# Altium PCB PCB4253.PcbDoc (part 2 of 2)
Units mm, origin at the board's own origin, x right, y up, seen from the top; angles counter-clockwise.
Board outline 30 x 51 mm, 6 copper layers (Top Layer, Signal Layer 2, GND Layer 3, PWR Layer 4, Signal Layer 5, Bottom Layer), stack 1.656 mm thick; 84 components, 108 nets, 396 pads, 436 vias.
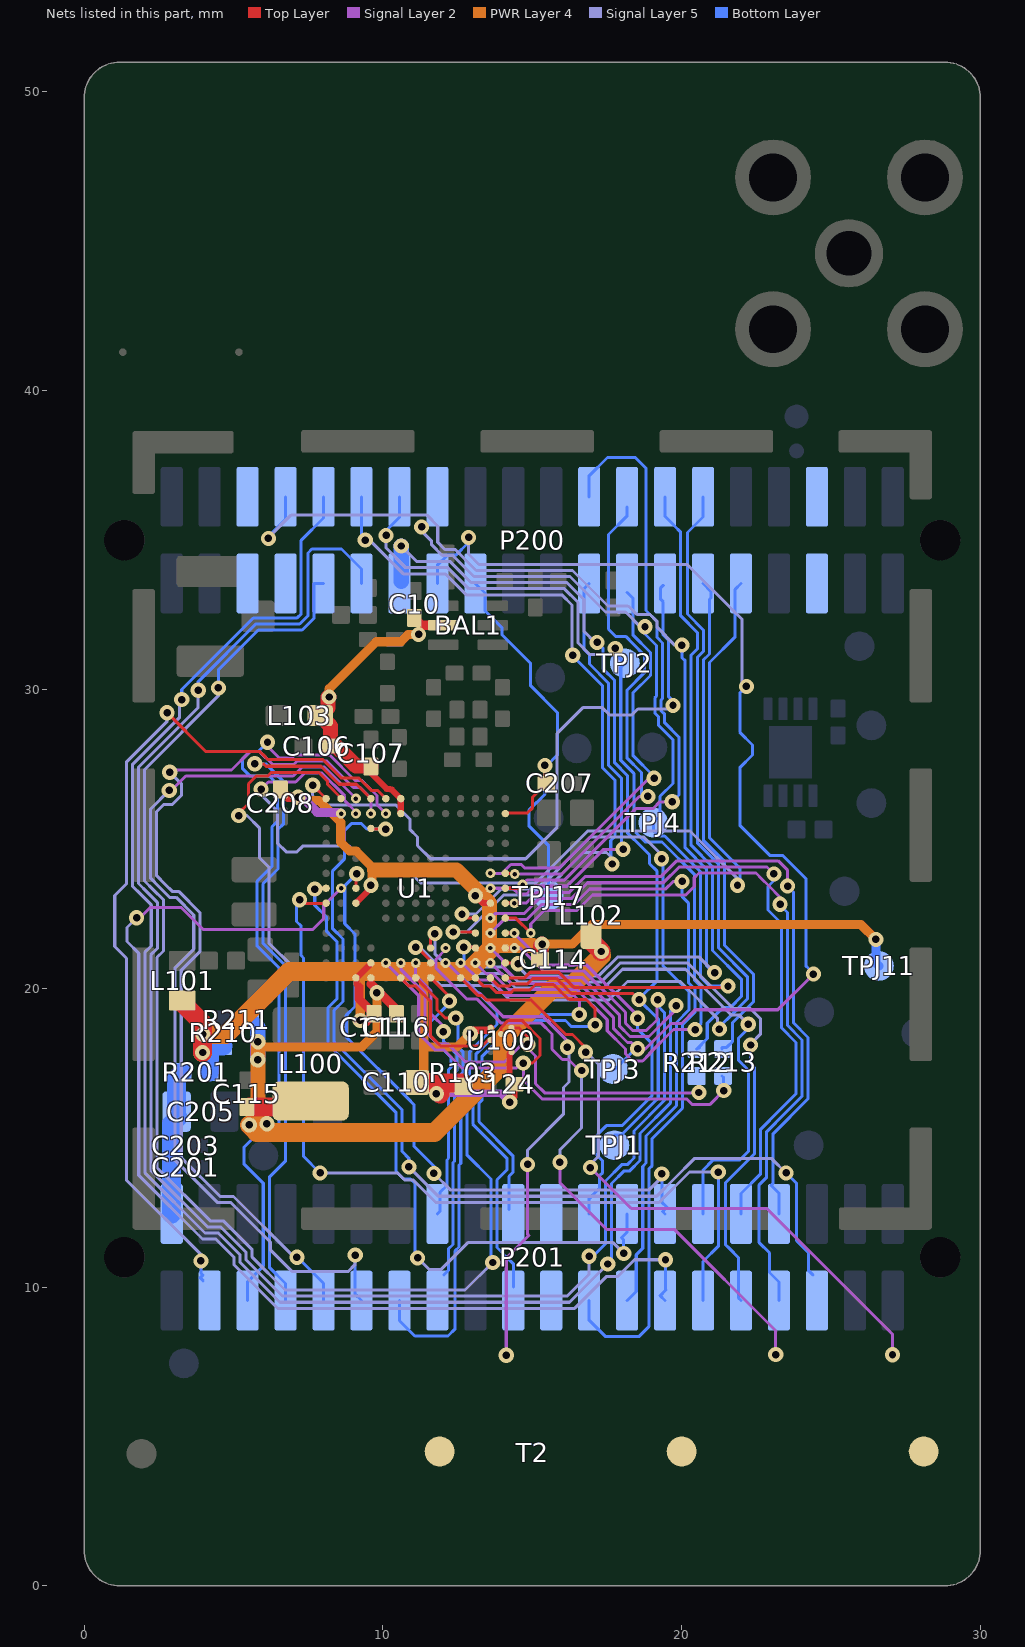
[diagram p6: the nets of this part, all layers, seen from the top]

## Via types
v1: diameter 0.508, hole 0.25, Top Layer to Bottom Layer, tented both sides, 404 vias
v2: diameter 0.33/0.33 (per signal layer), hole 0.15, Top Layer to Signal Layer 2, tented both sides, 31 vias
v3: diameter 0.33/0.33 (per signal layer), hole 0.15, Top Layer to Signal Layer 2, tented top, 1 vias

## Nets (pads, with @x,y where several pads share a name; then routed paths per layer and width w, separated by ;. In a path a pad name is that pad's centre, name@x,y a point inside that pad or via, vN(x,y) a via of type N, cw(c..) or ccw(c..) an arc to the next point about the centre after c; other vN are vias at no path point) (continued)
RADIO_PC1: T2.2 U1.B5 | length 16.6
  Signal Layer 2 w0.102: v2(12.1,20.85) 12.154,20.85 12.283,20.722 12.283,20.718 13.162,19.839 13.24,19.839 14.03,19.049 15.373,19.049 16.176,18.246 v1(16.176,18.026) ; v1(14.13,7.721) 14.13,10.974 14.884,11.728 14.845,11.767 v1(14.845,14.109)
  Signal Layer 5 w0.102: v1(14.845,14.109) 14.845,14.59 16.041,15.786 16.047,15.786 16.047,16.681 16.232,16.866 16.232,17.369 16.233,17.37 16.233,17.968 v1(16.176,18.026)
RADIO_PC2: T2.3 U1.C5 | length 21.5
  Signal Layer 2 w0.102: v3(12.1,21.35) 12.1,21.299 11.783,20.982 11.783,20.666 12.813,19.636 13.155,19.636 13.946,18.846 15.271,18.846 15.288,18.846 15.664,18.471 15.664,17.963 16.007,17.619 16.212,17.619 16.581,17.251 v1(16.651,17.251) ; v1(15.926,14.183) 15.926,13.494 16.239,13.181 17.484,11.936 19.753,11.936 23.159,8.531 23.148,8.519 v1(23.148,7.743)
  Signal Layer 5 w0.102: v1(15.926,14.183) 15.926,14.603 16.651,15.328 v1(16.651,17.251)
RADIO_PC3: T2.4 U1.A4 | length 22.7
  Top Layer w0.102: U1.A4@12.6,20.35 13.196,19.754 13.321,19.754 13.471,19.604 14.967,19.604 16.118,18.453 16.344,18.453 16.801,17.997 16.786,17.982 v1(16.786,17.861) ; v1@27.125,7.773 v1@27.166,7.732
  Signal Layer 2 w0.102: v1(16.949,14.001) 18.316,12.634 22.851,12.634 27.056,8.428 v1(27.056,7.736)
  Signal Layer 5 w0.102: v1(16.786,17.861) 16.816,17.861 17.218,17.459 17.218,14.379 16.949,14.11 v1(16.949,14.001)
RADIO_PC4: P201.19 U1.B4 | length 17.6
  Signal Layer 2 w0.102: v2(12.6,20.85) 12.651,20.85 13.225,20.276 13.614,20.276 14.13,19.76 16.394,19.76 16.576,19.578 v1(16.576,19.126)
  Bottom Layer w0.102: P201.19@14.365,10.004 14.365,10.785 13.821,11.329 13.821,13.591 14.149,13.92 14.149,14.317 13.013,15.453 13.013,15.621 13.015,15.622 13.015,16.235 13.11,16.331 13.11,17.796 14.44,19.126 v1(16.576,19.126)
RADIO_PC5: P201.20 U1.A3 | length 15.3
  Top Layer w0.102: U1.A3@13.1,20.35 13.377,20.073 13.59,20.073 13.794,19.868 14.298,19.868 14.373,19.944 14.918,19.944 15.106,20.132 15.717,20.132 16.223,19.626 16.797,19.626 17.101,19.322 v1(17.101,18.776)
  Bottom Layer w0.102: P201.20@14.224,12.591 14.224,13.707 14.352,13.835 14.352,14.401 13.217,15.537 13.218,15.538 13.218,16.151 13.313,16.246 13.313,17.712 14.524,18.923 16.111,18.923 16.315,18.72 17.044,18.72 v1(17.101,18.776)
RADIO_PC6: R213.1 U1.B9 U100.D2 | length 18.3
  Top Layer w0.102: U100.D2@13.958,18.471 13.958,18.685 14.201,18.928 14.648,18.928 15.257,18.319 15.257,17.749 15.009,17.501 v1(14.701,17.501)
  Signal Layer 2 w0.102: v2(10.1,20.85) 11.201,19.749 11.201,18.487 11.754,17.935 12.05,17.935 12.649,17.335 14.466,17.335 v1@14.683,17.551 ; v1(14.701,17.501) 14.701,16.93 15.331,16.3 20.172,16.3 20.364,16.108 20.936,16.108 v1(21.406,16.578)
  Bottom Layer w0.102: R213.1@21.351,17.065 21.406,17.01 v1(21.406,16.578)
RADIO_PC7: U1.A8 U100.C3 | length 4.7
  Top Layer w0.102: U1.A8@10.6,20.35 10.877,20.073 11.09,20.073 11.602,19.56 11.602,18.399 11.927,18.075 13.023,18.075 13.024,18.074 13.329,18.074 13.525,18.271 U100.C3@13.608,18.271
RADIO_PC8: R212.1 U1.B8 U100.E1 | length 14.7
  Top Layer w0.102: U100.E1@14.308,18.671 14.549,18.671 14.851,18.369 14.849,18.367 14.851,18.365 v1(14.851,18.126)
  Signal Layer 2 w0.102: v2(10.6,20.85) 10.6,20.637 11.405,19.833 11.405,18.571 11.838,18.138 12.175,18.138 12.775,17.538 14.07,17.538 14.682,18.151 14.826,18.151 v1(14.851,18.126) ; v1@14.771,18.071 15.107,17.735 15.107,16.811 15.415,16.503 20.566,16.503 v1(20.578,16.514)
RADIO_PC9: P201.13 U1.A7 | length 15.6
  Top Layer w0.102: U1.A7@11.1,20.35 11.806,19.644 11.806,19.293 12.096,19.003 v1(12.438,19.003)
  Bottom Layer w0.102: P201.13@10.555,9.55 10.555,8.879 11.071,8.363 12.18,8.363 12.421,8.603 12.421,11.216 12.551,11.346 12.551,14.09 12.607,14.146 12.607,17.108 12.688,17.189 12.688,17.863 12.519,18.032 12.519,18.922 v1(12.438,19.003)
RADIO_PC10: P201.15 U1.B7 | length 11.1
  Signal Layer 2 w0.102: v2(11.1,20.85) 11.1,20.425 11.608,19.917 11.608,19.149 v1@12.111,18.646
  Bottom Layer w0.102: v1(12.026,18.551) 12.026,18.238 12.485,17.778 12.485,17.273 12.404,17.192 12.404,14.23 12.347,14.174 12.347,11.43 12.192,11.275 12.192,10.557 P201.15@12.04,10.404
RADIO_PC11: P201.16 U1.A6 | length 9.3
  Top Layer w0.102: U1.A6@11.6,20.35 12.371,19.579 12.42,19.628 12.357,19.691 12.242,19.576 v1(12.226,19.576)
  Bottom Layer w0.102: P201.16@11.825,12.45 11.913,12.538 11.913,13.171 12.144,13.403 12.144,14.258 12.201,14.315 12.201,17.276 12.282,17.358 12.282,17.694 11.594,18.382 11.594,18.874 12.226,19.505 v1(12.226,19.576)
RADIO_PD8: P201.3 U1.N9 | length 29.7
  Top Layer w0.102: v1(2.781,29.223) 4.085,27.92 5.883,27.92 5.971,27.832 5.978,27.832 6.158,27.652 7.999,27.652 8.616,27.034 9.204,27.034 9.61,26.627 9.823,26.627 U1.N9@10.1,26.35
  Signal Layer 5 w0.102: v1(2.781,29.223) 2.781,28.936 1.415,27.569 1.415,23.493 1.028,23.106 1.028,21.401 1.424,21.005 1.424,13.577 3.988,11.013 3.933,10.959 3.977,10.916 3.938,10.877 v1(3.912,10.877)
  Bottom Layer w0.102: v1(3.912,10.877) 3.912,10.468 3.977,10.403 3.886,10.312 P201.3@3.988,10.21
RADIO_PD9: P201.5 U1.M9 | length 27.2
  Signal Layer 2 w0.102: v1(6.14,28.239) 6.14,28.105 6.544,27.701 6.941,27.701 7.054,27.813 8.211,27.813 9.068,26.956 9.299,26.956 9.803,26.452 9.803,26.147 v2(10.1,25.85)
  Bottom Layer w0.102: P201.5@5.475,9.55 5.475,10.182 5.997,10.704 5.997,13.48 5.348,14.13 5.348,14.67 5.7,15.023 ; 5.738,15.061 6.289,15.061 6.532,15.304 6.532,20.68 5.788,21.424 5.788,23.58 6.289,24.081 6.289,25.405 6.477,25.593 6.477,26.831 6.201,27.107 5.543,27.107 5.543,27.111 5.309,27.345 5.309,27.682 5.547,27.92 5.821,27.92 v1(6.14,28.239)
RADIO_PD10: P201.7 U1.N10 | length 24
  Top Layer w0.102: v1(5.715,27.514) 6.009,27.514 6.091,27.432 7.931,27.432 8.532,26.831 9.119,26.831 U1.N10@9.6,26.35
  Bottom Layer w0.102: v1(5.715,27.514) 6.082,27.514 6.68,26.915 6.68,25.509 6.492,25.321 6.492,23.997 5.992,23.496 5.992,21.508 6.735,20.764 6.735,14.213 6.201,13.678 6.201,10.664 6.745,10.12 P201.7@6.745,9.55
RADIO_PD11: P201.9 U1.M10 | length 30.4
  Signal Layer 2 w0.102: v1(2.87,27.234) 2.945,27.309 4.936,27.309 5.547,27.92 5.883,27.92 6.306,27.497 7.025,27.497 7.138,27.61 8.127,27.61 9.014,26.724 9.244,26.724 9.6,26.367 v2(9.6,25.85)
  Signal Layer 5 w0.102: v1(2.87,27.234) 3.257,26.848 3.257,26.456 2.953,26.153 2.666,26.153 2.431,25.918 2.431,23.764 2.723,23.472 2.947,23.248 3.168,23.248 3.875,22.541 3.875,21.229 3.253,20.607 3.253,14.335 4.556,13.031 5,13.031 7.031,11.001 v1(7.125,11.001)
  Bottom Layer w0.102: v1(7.125,11.001) 6.981,11.001 6.938,11.044 7.019,11.125 7.442,10.702 7.821,10.323 8.015,10.129 P201.9@8.015,9.55
RADIO_PD12: P201.11 U1.N11 | length 30.4
  Signal Layer 2 w0.102: v1(2.851,26.625) 2.925,26.625 3.406,27.106 6.031,27.106 ; 6.031,27.106 6.998,27.106 7.299,27.407 8.043,27.407 v2(9.1,26.35)
  Signal Layer 5 w0.102: v1(2.851,26.625) 2.228,26.002 2.228,23.68 2.519,23.388 2.863,23.045 3.084,23.045 3.672,22.456 3.672,21.313 3.05,20.691 3.05,14.25 4.472,12.828 4.916,12.828 6.235,11.508 6.235,11.254 6.97,10.52 8.832,10.52 9.075,10.763 v1(9.075,11.076)
  Bottom Layer w0.102: v1(9.075,11.076) 9.075,9.76 P201.11@9.285,9.55
RADIO_PD13: P200.31 U1.M11 | length 35
  Signal Layer 2 w0.102: v1(5.926,26.662) 6.166,26.903 7.082,26.903 7.384,27.204 7.959,27.204 8.721,26.441 8.721,26.28 9.1,25.901 v2(9.1,25.85)
  Signal Layer 5 w0.102: v1(5.926,26.662) 5.926,26.481 6.477,25.93 6.477,24.856 6.766,24.567 7.128,24.567 7.317,24.756 8.881,24.756 9.522,24.115 10.674,24.115 11.265,23.524 15.115,23.524 16.858,25.267 20.277,25.267 21.996,23.548 21.898,23.45 v1(21.869,23.45)
  Bottom Layer w0.102: v1(21.869,23.45) 21.951,23.45 21.951,24.016 20.93,25.038 20.93,30.903 21.79,31.763 21.79,33.355 P200.31@21.985,33.55
RADIO_PD14: P200.30 U1.N12 | length 46.3
  Top Layer w0.102: v1(5.179,25.782) 5.179,25.86 5.502,26.183 5.502,26.846 5.764,27.107 6.149,27.107 6.265,27.223 7.852,27.223 8.153,26.922 8.153,26.819 8.6,26.372 U1.N12@8.6,26.35
  Signal Layer 5 w0.102: v1(5.179,25.782) 5.456,25.782 5.867,25.371 5.867,24.378 6.198,24.048 6.198,21.502 6.965,20.735 11.298,20.735 11.936,20.097 13.76,20.097 14.25,19.607 17.564,19.607 18.189,20.232 19.958,20.232 21.206,18.984 21.206,18.821 21.342,18.685 v1@21.307,18.649 ; v1(21.263,18.634) 21.291,18.634 v1@21.307,18.649 ; v1@21.31,18.646 v1@21.307,18.649
  Bottom Layer w0.102: P200.30@20.715,36.45 20.715,35.776 20.193,35.254 20.193,32.53 20.727,31.996 20.727,31.276 20.523,31.072 20.523,24.869 21.238,24.155 21.238,21.35 22.2,20.388 22.2,19.641 21.708,19.15 21.706,19.15 21.285,18.729 21.34,18.674 21.31,18.644 21.305,18.649 21.29,18.634 v1(21.263,18.634)
RADIO_PD15: P200.27 U1.N13 | length 22.6
  Top Layer w0.102: v1(7.653,26.797) U1.N13@8.1,26.35
  Signal Layer 5 w0.102: v1(7.653,26.797) 7.653,26.438 7.948,26.142 10.429,26.142 10.905,25.666 10.905,25.319 11.163,25.062 11.163,24.776 11.602,24.337 14.778,24.337 15.834,25.393 15.834,28.535 16.693,29.394 17.345,29.394 17.595,29.145 18.33,29.145 18.533,29.348 19.589,29.348 v1(19.71,29.47)
  Bottom Layer w0.102: P200.27@19.384,33.489 19.298,33.403 19.298,33.022 19.383,32.937 19.383,31.826 19.565,31.643 19.565,29.755 v1@19.742,29.578
RADIO_PF0: P200.14 TPJ2.1 U1.B3 | length 36.2
  Signal Layer 2 w0.102: v2(13.1,20.85) 13.471,20.479 13.698,20.479 14.214,19.963 16.491,19.963 17.51,18.945 17.51,18.58 18.12,17.97 18.12,17.808 18.358,17.569 18.694,17.569 18.932,17.808 18.932,17.83 19.725,18.622 19.726,18.621 v1(20.45,18.621)
  Signal Layer 5 w0.102: v1(10.109,35.159) 10.109,34.737 10.77,34.076 12.175,34.076 12.877,33.374 16.076,33.374 16.535,32.915 16.535,31.558 16.922,31.171 17.577,31.171 v1(17.78,31.375)
  Bottom Layer w0.102: v1(10.109,35.159) 10.273,35.159 10.293,35.18 10.269,35.18 10.119,35.329 10.555,35.765 P200.14@10.555,36.45 ; v1(17.78,31.375) 17.751,31.375 17.678,31.302 TPJ2.1@18.1,30.88 17.961,30.741 17.961,29.353 17.961,28.509 17.961,27.631 18.398,27.195 18.398,25.28 18.78,24.898 19.345,24.898 20.425,23.818 20.425,20.281 20.653,20.053 20.653,18.835 20.45,18.632 v1(20.45,18.621)
RADIO_PF1: P200.13 TPJ1.1 U1.A2 | length 34
  Top Layer w0.102: U1.A2@13.6,20.35 13.878,20.072 14.214,20.072 14.289,20.147 14.834,20.147 15.022,20.335 15.802,20.335 16.307,19.829 18.373,19.829 v1(18.576,19.626)
  Signal Layer 5 w0.102: v1(10.617,34.804) 11.141,34.28 12.259,34.28 12.961,33.578 16.16,33.578 16.739,32.999 16.739,31.94 v1@17.093,31.585
  Bottom Layer w0.102: v1(17.17,31.578) 17.374,31.375 17.374,30.684 17.758,30.299 17.758,29.268 17.758,28.593 17.758,27.547 18.183,27.122 18.183,25.207 18.696,24.694 18.923,24.467 18.923,24.17 19.179,23.914 19.179,20.252 18.576,19.648 v1(18.576,19.626) ; TPJ1.1@17.75,14.75 17.75,15.093 17.982,15.093 19.217,16.328 19.217,18.971 18.566,19.621 v1@18.551,19.621
  Bottom Layer w0.508: P200.13@10.617,33.612 v1(10.617,34.804)
RADIO_PF2: P200.15 TPJ3.1 U1.B2 | length 40.6
  Signal Layer 2 w0.102: v2(13.6,20.851) 13.614,20.851 14.298,20.166 16.576,20.166 17.713,19.029 17.713,18.664 18.189,18.188 18.314,18.188 v1(18.526,17.976) 18.791,17.976 19.642,18.827 19.993,18.827 20.451,19.284 23.219,19.284 v1(24.411,20.476)
  Signal Layer 5 w0.102: v1(12.867,35.093) 12.867,34.534 13.213,34.187 20.183,34.187 22.017,32.352 22.017,30.252 v1(22.167,30.103)
  Bottom Layer w0.102: P200.15@11.825,33.55 11.825,34.16 12.162,34.497 12.444,34.497 12.867,34.92 v1(12.867,35.093) ; TPJ3.1@17.7,17.3 17.777,17.3 18.466,17.989 18.491,17.963 18.504,17.976 v1(18.526,17.976) 18.554,17.976 v1@18.593,18.014 ; v1(22.167,30.103) 21.946,29.881 21.946,28.574 22.372,28.147 22.372,27.812 21.946,27.385 21.946,25.458 22.963,24.441 23.391,24.441 24.155,23.677 24.155,20.754 v1@24.264,20.645
RADIO_PF3: P200.16 TPJ4.1 U1.A1 | length 31.1
  Top Layer w0.102: U1.A1@14.1,20.35 14.749,20.35 14.938,20.538 15.886,20.538 16.392,20.032 21.507,20.032 v1(21.551,20.076)
  Signal Layer 5 w0.102: v1(11.297,35.441) 11.384,35.441 11.384,35.217 11.634,34.967 11.634,34.841 11.992,34.483 12.343,34.483 13.045,33.781 16.263,33.781 17.45,32.594 18.126,32.594 18.617,32.103 v1(18.773,32.103)
  Bottom Layer w0.102: v1(18.773,32.103) 18.773,31.861 19.159,31.475 19.159,29.78 19.101,29.722 19.101,29.217 19.228,29.09 19.228,28.804 19.71,28.321 19.71,26.856 19.279,26.424 19.279,26.075 19.28,26.074 19.28,25.78 TPJ4.1@19.05,25.55 19.05,25.285 19.234,25.101 19.43,25.101 20.628,23.902 20.628,20.366 20.918,20.076 v1(21.551,20.076)
RADIO_PF4: P200.23 U1.G2 | length 14.7
  Signal Layer 2 w0.102: v2(13.6,23.35) 14.351,23.35 14.544,23.157 14.808,23.157 15.068,23.417 16.155,23.417 17.391,24.653 v1(18.042,24.653)
  Bottom Layer w0.102: P200.23@16.905,33.55 16.739,33.384 16.739,31.34 16.916,31.162 16.916,30.854 17.555,30.215 17.555,29.184 17.555,28.677 17.555,27.463 17.98,27.038 17.98,24.697 18.024,24.653 v1(18.042,24.653)
RADIO_PF5: P200.24 U1.G1 | length 21.7
  Top Layer w0.102: U1.G1@14.1,23.35 14.55,23.35 v2(14.675,23.475) ; v2@14.667,23.5 v2@14.675,23.492 ; v2(14.675,23.475) v2@14.675,23.492 ; v2(14.675,23.475) 14.683,23.483 v2@14.675,23.492
  Signal Layer 2 w0.102: v2@14.71,23.44 v2(14.675,23.475) 14.821,23.621 16.071,23.621 18.466,26.015 19.041,26.015 19.269,26.244 v1(19.685,26.244)
  Bottom Layer w0.102: P200.24@16.905,36.45 16.905,37.155 17.519,37.769 18.449,37.769 18.808,37.409 18.808,32.645 19.179,32.274 19.179,31.742 19.362,31.559 19.362,29.696 19.304,29.638 19.304,29.301 19.431,29.174 19.431,28.888 19.914,28.405 19.914,26.472 v1(19.685,26.244)
RADIO_PF6: P200.25 U1.H2 | length 14
  Signal Layer 2 w0.102: v2(13.6,23.85) 13.99,23.85 14.282,24.141 14.635,24.141 14.749,24.027 15.903,24.027 18.907,27.031 v1(19.075,27.031)
  Bottom Layer w0.102: P200.25@18.175,33.25 18.364,33.061 18.364,31.83 18.956,31.239 18.956,30.473 18.368,29.885 18.368,28.34 18.368,27.8 19.075,27.092 v1(19.075,27.031)
RADIO_PF7: P200.26 U1.H1 | length 17.1
  Top Layer w0.102: U1.H1@14.1,23.85 14.387,23.85 v2(14.413,23.824)
  Signal Layer 2 w0.102: v2(14.413,23.824) 15.987,23.824 18.585,26.422 v1(18.872,26.422)
  Bottom Layer w0.102: P200.26@18.175,36.114 18.175,35.812 17.551,35.188 17.551,32.019 17.789,31.781 18.126,31.781 18.364,31.543 18.364,31.538 18.752,31.15 18.752,30.557 18.164,29.969 18.164,29.437 18.164,28.424 18.164,27.716 18.659,27.221 18.659,26.422 v1@18.791,26.422
RADIO_PF8: P200.8 U1.B1 | length 38
  Top Layer w0.102: U1.B1@14.1,20.85 14.563,20.85 14.601,20.812 14.661,20.872 14.614,20.826 v1(14.526,20.826)
  Signal Layer 5 w0.102: v1(6.172,35.058) 6.172,35.082 6.938,35.848 11.465,35.848 11.837,35.475 11.837,34.925 12.076,34.686 12.427,34.686 13.129,33.984 16.347,33.984 17.534,32.797 18.21,32.797 18.498,32.509 18.941,32.509 19.179,32.271 19.179,32.08 19.773,31.486 v1(20.007,31.486) ; v1(14.526,20.826) 14.651,20.826 14.661,20.836 14.602,20.778 14.605,20.778 14.539,20.712 14.48,20.772 14.478,20.77 14.828,20.42 17.228,20.42 17.852,21.045 20.586,21.045 v1(21.104,20.526)
  Bottom Layer w0.102: v1@6.125,35.075 6.745,35.695 P200.8@6.745,36.45 ; v1(20.007,31.486) 20.007,31.074 20.117,30.965 20.117,24.701 20.831,23.986 20.831,20.754 21.104,20.481 v1(21.104,20.526)
RADIO_PF9: P200.9 U1.C3 | length 49.1
  Top Layer w0.102: v1(12.708,21.381) 13.069,21.381 U1.C3@13.1,21.35
  Signal Layer 5 w0.102: v1(4.496,30.054) 4.496,29.788 2.024,27.317 2.024,23.596 2.316,23.304 2.656,22.965 2.656,21.252 2.44,21.036 2.44,13.998 4.22,12.218 4.663,12.218 5.626,11.256 5.626,11.002 6.726,9.902 12.752,9.902 v1(13.676,10.826)
  Bottom Layer w0.102: v1(4.496,30.054) 4.496,30.65 5.835,31.99 7.302,31.99 7.696,32.384 7.696,33.55 P200.9@8.015,33.55 ; v1(12.708,21.381) 12.708,20.324 13.818,19.215 13.818,18.792 12.907,17.881 12.907,16.415 12.811,16.319 12.811,15.706 12.81,15.705 12.81,15.368 12.81,14.427 13.617,13.62 13.617,10.884 v1(13.676,10.826)
RADIO_PF10: P200.10 U1.C2 | length 62.4
  Signal Layer 2 w0.102: v2(13.6,21.35) 13.998,20.952 13.998,20.754 14.382,20.37 16.66,20.37 17.916,19.113 17.916,18.748 18.273,18.391 18.909,18.391 19.815,19.298 v1(19.815,19.423)
  Signal Layer 5 w0.102: v1(3.27,29.664) 3.188,29.582 3.188,29.055 1.618,27.485 1.618,23.428 1.91,23.136 2.249,22.796 2.249,21.42 2.034,21.205 2.034,13.83 4.051,11.812 4.495,11.812 5.219,11.087 5.219,10.833 6.558,9.495 16.246,9.495 v1(17.526,10.775)
  Bottom Layer w0.102: v1(3.27,29.664) 3.27,29.999 5.667,32.396 6.521,32.396 6.523,32.398 7.135,32.398 7.267,32.53 7.267,34.992 8.015,35.74 P200.10@8.015,36.45 ; v1(17.526,10.775) 17.653,10.902 17.653,13.47 18.077,13.894 18.264,13.894 18.606,14.236 18.606,15.142 19.623,16.159 19.623,19.231 v1(19.815,19.423)
RADIO_PF11: P200.11 U1.C1 | length 61.4
  Top Layer w0.102: U1.C1@14.1,21.35 v2(14.4,21.35)
  Signal Layer 2 w0.102: v2(14.4,21.35) 14.599,21.35 15.376,20.573 16.744,20.573 18.12,19.197 18.12,18.833 18.358,18.595 18.824,18.595 19.174,18.944 19.174,19.585 v1(19.205,19.617)
  Signal Layer 5 w0.102: v1(3.821,29.975) 3.821,29.401 1.821,27.401 1.821,23.512 2.113,23.22 2.453,22.88 2.453,21.336 2.237,21.12 2.237,13.914 4.135,12.015 4.579,12.015 5.423,11.172 5.423,10.918 6.642,9.699 16.162,9.699 16.903,10.44 v1(16.903,11.033)
  Bottom Layer w0.102: v1(3.821,29.975) 3.821,30.263 5.751,32.193 7.217,32.193 7.493,32.468 7.493,34.57 7.625,34.702 8.618,34.702 9.285,34.036 P200.11@9.285,33.55 ; v1(16.903,11.033) 17.03,11.033 17.449,11.452 17.449,13.554 17.993,14.098 18.18,14.098 18.402,14.32 18.402,15.226 19.42,16.244 19.42,19.192 19.205,19.406 v1(19.205,19.617)
RADIO_PF12: P200.12 U1.D3 | length 26.1
  Top Layer w0.102: v1(12.351,21.885) 13.065,21.885 U1.D3@13.1,21.85
  Signal Layer 5 w0.102: v1(9.414,35) 9.559,35 10.686,33.873 12.091,33.873 12.793,33.171 15.992,33.171 16.332,32.831 16.332,31.171 v1(16.358,31.146) ; v1(12.351,21.885) 12.807,21.885 14.039,23.118 15.283,23.118 16.714,24.548 17.484,24.548 17.671,24.361 v1(17.671,24.162)
  Bottom Layer w0.102: P200.12@9.285,36.45 9.285,35.129 v1(9.414,35) ; v1(16.358,31.146) 16.358,31.125 17.352,30.131 17.352,29.1 17.352,28.761 17.352,27.379 17.777,26.954 17.777,25.097 17.627,24.946 17.627,24.207 v1(17.671,24.162)
RADIO_PF13: P201.23 U1.D2 | length 25.9
  Signal Layer 2 w0.102: v2(13.6,21.85) 14.047,22.297 14.809,22.297 15.32,22.808 16.408,22.808 16.93,23.33 19.47,23.33 19.717,23.577 v1(20.015,23.577)
  Bottom Layer w0.102: P201.23@16.905,9.55 16.905,8.892 17.455,8.342 18.564,8.342 18.901,8.678 18.901,13.956 19.012,14.068 19.012,14.974 20.029,15.991 20.029,18.775 20.45,19.196 20.45,19.969 20.222,20.197 20.222,22.861 20.015,23.067 v1(20.015,23.577)
RADIO_PF14: P201.24 U1.D1 | length 13.8
  Top Layer w0.102: U1.D1@14.1,21.85 v2(14.4,21.85)
  Signal Layer 2 w0.102: v2(14.4,21.85) 14.4,21.837 15.461,20.776 16.828,20.776 18.526,19.078 v1(18.526,19.001) v1@18.538,19.001
  Bottom Layer w0.102: P201.24@16.905,12.45 16.905,12.961 17.246,13.302 17.246,13.724 17.355,13.832 17.355,14.222 17.098,14.48 17.098,15.02 17.48,15.402 18.004,15.402 19.013,16.412 19.013,18.146 18.526,18.633 v1(18.526,19.001)
RADIO_PF15: P201.25 U1.E3 | length 24.7
  Top Layer w0.102: v1(12.649,22.485) 12.715,22.485 12.85,22.35 U1.E3@13.1,22.35
  Signal Layer 5 w0.102: v1(12.649,22.485) 13.118,22.485 13.955,23.321 15.199,23.321 16.942,25.064 18.731,25.064 19.329,24.466 v1(19.329,24.339)
  Bottom Layer w0.102: P201.25@18.175,9.55 18.481,9.856 18.481,11.081 18.697,11.298 18.697,14.04 18.809,14.152 18.809,15.058 19.826,16.075 19.826,18.86 20.247,19.28 20.247,19.885 19.382,20.749 19.382,24.286 v1(19.329,24.339)
RADIO_PI0: P201.26 U1.G13 | length 23.6
  Top Layer w0.102: v1(7.722,23.323) 7.749,23.35 U1.G13@8.1,23.35
  Signal Layer 5 w0.102: v1@11.187,10.98 v1(11.161,10.98) 11.544,10.597 11.959,10.597 12.862,11.501 17.689,11.501 v1(18.059,11.131)
  Bottom Layer w0.102: v1(7.722,23.323) 7.722,22.78 8.115,22.386 8.115,21.911 8.46,21.566 8.46,19.643 8.165,19.348 8.165,18.125 8.186,18.104 10.435,15.856 10.435,13.888 10.703,13.62 10.927,13.62 11.077,13.47 11.077,11.064 v1(11.161,10.98) ; v1(18.059,11.131) 18.059,11.581 17.985,11.655 18.175,11.845 P201.26@18.175,12.45
RADIO_PI1: P201.27 U1.G12 | length 38.8
  Signal Layer 2 w0.102: v1(1.758,22.36) 1.876,22.36 2.226,22.709 3.246,22.709 3.98,21.975 7.659,21.975 8.022,22.337 8.022,22.772 v2(8.6,23.35)
  Signal Layer 5 w0.102: v1(1.758,22.36) 1.437,22.039 1.437,21.568 1.83,21.174 1.83,13.745 3.967,11.609 4.411,11.609 5.016,11.003 5.016,10.749 6.474,9.292 16.418,9.292 17.49,10.364 17.867,10.364 18.42,10.917 v1(19.459,10.917)
  Bottom Layer w0.102: P201.27@19.445,9.55 19.28,9.715 19.475,9.911 19.459,9.927 v1(19.459,10.917)
RADIO_PI2: P201.28 U1.G11 | length 21.9
  Top Layer w0.102: U1.G11@9.1,23.35 9.1,23.85 9.119,23.831 v1(9.125,23.837)
  Signal Layer 5 w0.102: v1(11.709,13.806) 12.27,13.245 18.903,13.245 19.335,13.677 v1(19.335,13.788)
  Bottom Layer w0.102: v1(9.125,23.837) 8.725,23.437 8.725,22.163 9.07,21.818 9.07,19.391 8.775,19.096 8.775,18.378 8.796,18.357 10.83,16.323 11.044,16.108 11.044,14.716 11.709,14.051 v1(11.709,13.806) ; v1(19.335,13.788) 19.335,12.845 19.507,12.674 19.364,12.531 P201.28@19.445,12.45
RADIO_PI3: P201.29 U1.F13 | length 29.4
  Top Layer w0.102: v1(7.214,22.967) 7.217,22.967 7.237,22.947 7.134,22.844 7.176,22.844 7.274,22.942 7.372,22.844 8.094,22.844 U1.F13@8.1,22.85
  Signal Layer 5 w0.102: v1(7.899,13.823) 10.5,13.823 10.744,13.579 11.024,13.579 11.765,12.838 19.248,12.838 20.26,13.851 v1(21.226,13.851)
  Bottom Layer w0.102: v1(7.214,22.967) 7.112,22.866 7.112,22.24 7.265,22.087 7.265,21.435 ; 7.264,21.434 7.264,21.097 7.345,21.017 7.345,14.378 v1(7.899,13.823) ; P201.29@20.715,9.55 20.715,10.862 21.237,11.384 21.237,13.839 v1(21.226,13.851)
RADIO_PJ14: P201.30 U1.B6 | length 21.3
  Top Layer w0.102: v1(11.094,21.371) 11.148,21.371 11.6,20.919 U1.B6@11.6,20.85
  Signal Layer 5 w0.102: v1(11.094,21.371) 11.237,21.371 12.104,20.503 13.947,20.503 14.437,20.014 17.396,20.014 18.021,20.638 20.126,20.638 21.652,19.113 21.914,19.113 v1(22.226,18.801)
  Bottom Layer w0.102: P201.30@20.715,12.45 20.715,13.914 21.062,14.262 21.951,14.262 22.235,14.546 22.235,17.261 21.895,17.601 21.895,18.119 21.902,18.127 21.902,18.335 22.226,18.659 v1(22.226,18.801)
RADIO_PJ15: P201.31 U1.C6 | length 24.2
  Top Layer w0.102: U1.C6@11.585,21.365 U1.C6@11.6,21.35 11.6,21.689 v1(11.741,21.831)
  Signal Layer 5 w0.102: v1(11.741,21.831) 11.741,21.154 12.188,20.707 14.031,20.707 14.521,20.217 17.312,20.217 17.937,20.842 20.211,20.842 21.736,19.317 22.305,19.317 22.632,18.989 22.632,18.461 22.338,18.166 22.429,18.075 22.305,17.951 22.284,17.972 22.309,17.996 v1(22.309,18.104)
  Bottom Layer w0.102: P201.31@21.985,9.55 21.905,9.63 21.905,10.987 21.595,11.297 21.463,11.43 21.463,13.486 22.438,14.462 22.438,17.345 22.301,17.482 22.301,17.951 22.284,17.968 22.309,17.992 v1(22.309,18.104)
RADIO_PK0: P201.32 U1.E2 | length 22.9
  Signal Layer 2 w0.102: v2(13.6,22.35) 13.75,22.5 14.725,22.5 15.236,23.011 16.324,23.011 16.846,23.534 19.386,23.534 19.916,24.063 22.856,24.063 v1(23.089,23.831)
  Bottom Layer w0.102: P201.32@21.985,12.45 21.985,13.137 22.643,13.795 22.643,15.289 23.25,15.895 23.41,16.056 23.825,16.471 23.825,18.19 23.338,18.677 23.338,22.17 22.886,22.621 22.886,23.409 23.089,23.611 v1(23.089,23.831)
RADIO_PK1: P201.33 U1.E1 | length 25.6
  Top Layer w0.102: U1.E1@14.1,22.35 14.45,22.35 v2(14.95,21.85)
  Signal Layer 2 w0.102: v2(14.95,21.85) 14.95,22.15 15.404,22.605 16.492,22.605 17.015,23.127 20.14,23.127 20.422,23.408 20.422,23.703 20.578,23.86 22.485,23.86 22.682,23.663 22.92,23.424 23.293,23.052 v1(23.293,22.815)
  Bottom Layer w0.102: P201.33@23.255,9.55 23.255,10.172 22.937,10.49 22.937,11.148 22.595,11.491 22.595,13.425 22.846,13.676 22.846,15.205 23.453,15.811 23.495,15.853 24.028,16.387 24.028,18.274 23.541,18.761 23.541,22.54 23.293,22.789 v1(23.293,22.815)
RADIO_PK2: P201.34 U1.F1 | length 22.3
  Top Layer w0.102: U1.F1@14.1,22.85 v2(14.4,22.85)
  Signal Layer 2 w0.102: v2(14.4,22.85) 14.788,22.85 15.152,23.214 16.239,23.214 16.762,23.737 19.302,23.737 19.831,24.266 23.228,24.266 23.546,23.948 v1(23.546,23.424)
  Bottom Layer w0.102: P201.34@23.255,12.45 23.255,13.145 22.993,13.407 23.049,13.463 23.049,15.12 24.232,16.303 24.232,18.358 23.744,18.846 23.744,23.231
USB_VBUS: P200.35
USB_VREG: P200.36
VBIAS: BAL1.2 C10.1 C106.1 C107.1 L103.2 U1.M8 U1.N8 | length 10.8
  Top Layer w0.203: C107.1@9.6,27.425 9.6,27.209 10.131,26.678 10.236,26.678 10.264,26.65 10.3,26.65 U1.N8@10.6,26.35 U1.M8@10.6,25.85 ; C10.1@11.05,32.4 C10.1@11.125,32.325
  Top Layer w0.305: C10.1@11.125,32.325 11.3,32.15 BAL1.2@12.024,32.15
  Top Layer w0.508: v1(8.2,29.75) 8.166,29.75 8.166,29.391 L103.2@7.9,29.125 8.243,28.782 C106.1@8.243,28.107 8.438,28.107 9.105,27.44 9.6,27.44 C107.1@9.6,27.425
  PWR Layer 4 w0.305: v1(8.2,29.75) 8.2,30.025 9.775,31.6 10.6,31.6 10.845,31.845 v1(11.195,31.845)
VDCDC: C115.1 C116.1 L100.2 L102.1 R211.2 U1.A10 | length 28
  Top Layer w0.203: U1.A10@9.6,20.35 9.6,20.15 9.606,20.144
  Top Layer w0.305: 9.606,20.15 9.606,20.144 v1@9.8,19.95 ; v1(9.8,19.85) v1@9.8,19.95 ; C116.1@10.45,19.15 10.45,19.3 v1@9.8,19.95
  Top Layer w0.635: C115.1@5.532,16.025 L100.2@6.949,16.025 ; L102.1@16.972,21.746 16.972,21.573 17.304,21.241 v1@17.304,21.233
  PWR Layer 4 w0.305: 6.083,18.036 9.298,18.036 9.8,18.538 v1(9.8,19.85)
  PWR Layer 4 w0.508: 5.819,15.467 v1(5.819,18.212)
  PWR Layer 4 w0.635: v1(5.532,15.429) 5.778,15.183 11.73,15.183 14.009,17.462 14.009,18.327 15.666,19.984 16.206,19.984 v1@17.313,21.091
  Bottom Layer w0.508: R211.2@5.558,18.955 5.813,18.701 v1(5.813,17.611)
  other v1: 6.121,15.467 17.313,21.233
VMCU: C110.1 C111.1 C114.1 C124.1 C208.1 L101.1 R103.1 R201.2 R210.2 TPJ11.1 U1.A11 U1.B10 U1.F2 U1.F11 U1.M12 U100.A1 U100.E3 | length 61.6
  Top Layer w0.203: U1.F11@9.1,22.85 9.6,23.35 v1(9.6,23.45) ; 9.2,20.05 9.121,20.129 9.121,20.329 U1.A11@9.1,20.35 9.121,20.35 9.6,20.829 U1.B10@9.6,20.85 ; v1(13.1,23.1) 13.35,22.85 U1.F2@13.6,22.85 ; C124.1@14.289,16.673 C124.1@14.289,16.791 ; U100.A1@14.308,17.871 14.244,17.807 14.244,16.959 C124.1@14.411,16.791 14.411,16.359 v1@14.272,16.219 ; v1@14.272,16.219 14.298,16.193 v1(14.245,16.193) v1@14.272,16.219
  Top Layer w0.254: v1(12.926,18.481) 13.049,18.604 13.541,18.604 U100.E3@13.608,18.671
  Top Layer w0.305: C208.1@6.569,26.651 6.824,26.396 v1(7.163,26.396) ; 9.2,20.05 9.2,19.65 C111.1@9.7,19.15 v1@9.429,18.879
  Top Layer w0.508: C114.1@15.284,20.972 15.284,21.434 v1(15.33,21.481)
  Top Layer w0.635: L101.1@3.285,19.511 3.97,18.826 ; v1(3.97,17.853) 3.97,18.815 ; C110.1@11.15,16.85 11.921,16.85 ; v1@11.921,16.471 11.921,16.85 ; R103.1@12.679,16.837 11.933,16.837 11.921,16.85
  Signal Layer 2 w0.254: v1@11.81,16.489 13.949,16.489 v1(14.245,16.193) ; v1@11.877,16.428 v1@11.915,16.465
  Signal Layer 2 w0.305: v1(7.163,26.396) 7.297,26.396 7.805,25.888 8.562,25.888 v2(8.6,25.85)
  PWR Layer 4 w0.305: 7.409,26.289 7.858,26.289 8.592,25.555 8.592,24.89 8.89,24.592 9.111,24.592 9.633,24.069 v1@9.633,23.483 ; 9.209,20.563 9.246,20.527 v1(9.246,18.929) ; 11.367,20.563 11.367,16.937 v1@11.877,16.428 ; 11.389,18.043 12.487,18.043 v1(12.926,18.481) ; v1(15.33,21.481) 16.337,21.481 16.907,22.051 16.911,22.051 16.994,22.134 26.002,22.134 v1(26.499,21.637)
  PWR Layer 4 w0.508: 9.723,23.96 12.468,23.96 13.57,22.857 13.57,21.373 13.617,21.326 ; 13.693,21.402 13.727,21.436 15.028,21.436 15.062,21.402 v1@15.33,21.402
  PWR Layer 4 w0.635: v1(3.97,17.853) v1@3.97,18.457 ; v1(3.977,18.457) 4.753,18.457 6.864,20.569 8.129,20.569 8.135,20.563 9.209,20.563 12.855,20.563 13.617,21.326 13.693,21.402
  Bottom Layer w0.305: v1(26.499,21.637) 26.499,20.85 TPJ11.1@26.6,20.75
  Bottom Layer w0.635: v1(3.977,18.457) 3.977,17.861 4.182,18.066 R210.2@4.658,18.066 ; R201.2@4.2,17.2 v1@4.2,17.853
  other v1: 11.794,16.474
VMCU_IN: C201.1 C203.1 C205.1 P201.2 R201.1 | length 4.7
  Bottom Layer w0.635: P201.2@2.935,12.45 2.933,12.452 2.933,15.469 C205.1@3.139,15.674 ; C205.1@3.1,15.875 3.1,17 R201.1@3.3,17.2
WSTK_F4: C207.1 P200.17 TPJ17.1 U1.M1 | length 15.2
  Top Layer w0.102: U1.M1@14.1,25.85 14.119,25.869 14.837,25.869 15.015,26.047 15.015,26.404 C207.1@15.309,26.698 ; v1(15.423,27.461) 15.423,27.077 C207.1@15.556,26.945 ; C207.1@15.468,26.857 C207.1@15.309,26.698 ; C207.1@15.5,27 15.309,26.809 C207.1@15.309,26.698
  Bottom Layer w0.102: P200.17@13.095,33.55 13.418,33.227 13.418,32.636 13.992,32.063 13.992,31.825 14.948,30.869 14.948,30.124 15.838,29.234 15.838,27.807 15.492,27.461 v1(15.423,27.461) 15.423,26.499 14.898,25.973 14.898,25.423 15.55,24.771 TPJ17.1@15.55,23.1
WSTK_F15: P200.28 R212.2 | length 20.6
  Bottom Layer w0.102: P200.28@19.445,36.45 19.445,35.794 19.744,35.496 19.744,35.491 19.967,35.267 19.967,32.468 20.524,31.911 20.524,31.36 20.32,31.156 20.32,24.785 21.035,24.07 21.035,21.266 21.996,20.304 21.996,19.725 21.624,19.353 21.373,19.353 20.856,18.836 20.856,18.751 20.856,18.363 20.858,18.361 20.858,18.32 R212.2@20.504,17.966 20.59,18.051 R212.2@20.59,18.009
WSTK_F16: P200.29 R213.2 | length 17
  Bottom Layer w0.102: P200.29@20.715,33.55 20.975,33.29 20.975,33.064 20.93,33.02 20.93,31.191 20.726,30.987 20.726,24.953 21.441,24.239 21.441,21.434 22.403,20.473 22.403,19.551 22.059,19.207 ; R213.2@21.351,17.965 21.351,18.027 21.508,18.027 21.699,18.218 21.699,18.849 22.058,19.207
WSTK_P18: P201.21
WSTK_P19: P201.22
WSTK_P32: P201.35 U1.L10 | length 32.3
  Top Layer w0.102: U1.L10@9.6,25.35 9.648,25.302 9.676,25.329 v1(10.092,25.329)
  Signal Layer 5 w0.102: v1(10.871,14.026) 11.856,13.042 19.164,13.042 19.742,13.62 20.421,14.299 23.019,14.299 v1(23.495,13.823)
  Bottom Layer w0.102: v1(10.092,25.329) 9.465,25.329 9.284,25.511 8.947,25.511 8.709,25.273 8.709,24.321 8.319,23.931 8.319,21.995 8.663,21.65 8.663,19.559 8.368,19.264 8.368,18.209 8.389,18.188 10.638,15.94 10.638,14.547 10.871,14.314 v1(10.871,14.026) ; v1(23.495,13.823) 23.849,13.47 23.849,11.557 24.238,11.168 24.238,10.563 P201.35@24.388,10.413
WSTK_P38: P200.5
WSTK_P39: P200.6
WSTK_P40: P200.7
pads on no net: BAL1.6 P200.M1 P200.M2 P201.40 P201.M1 P201.M2 TPJ9.1 TPJ18.1 TPJ19.1 TPJ20.1 U100.C1 U200.9

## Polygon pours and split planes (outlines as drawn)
GND on Top Layer "GND_L1" (solid, remove dead copper, pour order 29): 0.605,40.64 20.99,40.64 ccw(c20.99,41.507) 21.857,41.507 21.857,46.54 23.657,48.34 27.557,48.34 29.357,46.54 29.355,9 cw(c28.848,8.999) 28.848,8.492 1.109,8.492 cw(c1.109,8.996) 0.605,8.996
GND on GND Layer 3 "GND_L3" (solid, remove dead copper, pour order 25): 0.605,40.64 20.99,40.64 ccw(c20.99,41.507) 21.857,41.507 21.857,46.54 23.657,48.34 27.557,48.34 29.357,46.54 29.355,8.855 cw(c29,8.855) 29,8.5 1,8.5 cw(c1,8.895) 0.605,8.895
GND on Bottom Layer "GND_L6" (solid, remove dead copper, pour order 24): 0.605,40.64 20.99,40.64 ccw(c20.99,41.507) 21.857,41.507 21.857,46.54 23.657,48.34 27.557,48.34 29.357,46.54 29.357,8.261 0.605,8.261
GND on Bottom Layer "Bottom Layer-GND_Mesh" (hatched 90Degree grid 1 track 0.2, pour order 39): 0.704,8.229 0.704,1.38 ccw(c1.339,1.38) 1.339,0.744 28.62,0.744 ccw(c28.62,1.38) 29.255,1.38 29.255,8.229
GND on PWR Layer 4 "GND_L4" (solid, remove dead copper, pour order 33): 0.605,40.64 20.99,40.64 ccw(c20.99,41.507) 21.857,41.507 21.857,46.54 23.657,48.34 27.557,48.34 29.357,46.54 29.355,8.855 cw(c29,8.855) 29,8.5 1,8.5 cw(c1,8.895) 0.605,8.895
GND on Signal Layer 2 "GND_L2" (solid, remove dead copper, pour order 37): 0.605,40.64 20.99,40.64 ccw(c20.99,41.507) 21.857,41.507 21.857,46.54 23.657,48.34 27.557,48.34 29.357,46.54 29.355,8.855 cw(c29,8.855) 29,8.5 1,8.5 cw(c1,8.895) 0.605,8.895
GND on Signal Layer 5 "GND_L5" (solid, remove dead copper, pour order 35): 0.605,40.64 20.99,40.64 ccw(c20.99,41.507) 21.857,41.507 21.857,46.54 23.657,48.34 27.557,48.34 29.357,46.54 29.355,8.855 cw(c29,8.855) 29,8.5 1,8.5 cw(c1,8.895) 0.605,8.895

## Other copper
Top Layer:
  pour cut-out: 8.826,32.95 10.05,32.95 10.05,31.375 10.819,31.375 10.819,33.341 11.219,33.341 11.219,34.275 17.519,34.275 17.519,33.05 14.85,33.05 14.85,30.6 15.15,30.6 15.15,26.056 14.119,26.056 14.119,20.35 10.05,20.35 10.05,18.534 8.119,18.534 8.119,29.031 9.45,29.031 9.45,30.725 8.826,31.349
  region net VDCDC: 5.201,16.339 5.201,15.274 5.343,15.132 6.24,15.132 6.407,15.299 6.407,16.342
Signal Layer 2:
  pour cut-out: 0,31.483 0,41.202 21.75,41.202 21.75,48.5 30,48.5 30,32.443 15.15,32.443 15.15,25.75 8,25.75 8,29.031 9.456,29.031 9.456,30.647 8.702,31.483
GND Layer 3:
  pour cut-out: 3.026,33.299 3.026,31.599 5.13,31.599 5.13,31.868 6.426,31.869 6.426,33.037 5.13,33.037 5.13,33.298
  pour cut-out: 11.75,26.075 11.75,28.3 ccw(c11.525,28.3) 11.525,28.525 cw(c11.525,28.775) 11.275,28.775 11.275,30.35 cw(c11.525,30.35) 11.525,30.6 14.875,30.6 cw(c14.875,30.325) 15.15,30.325 15.155,26.48 cw(c14.525,26.48) 14.525,25.85 11.975,25.85 cw(c11.975,26.075)
PWR Layer 4:
  pour cut-out: 11.75,26.075 11.75,28.3 ccw(c11.525,28.3) 11.525,28.525 cw(c11.525,28.775) 11.275,28.775 11.275,30.35 cw(c11.525,30.35) 11.525,30.6 14.875,30.6 cw(c14.875,30.325) 15.15,30.325 15.155,26.48 cw(c14.525,26.48) 14.525,25.85 11.975,25.85 cw(c11.975,26.075)
Signal Layer 5:
  pour cut-out: 11.75,26.075 11.75,28.3 ccw(c11.525,28.3) 11.525,28.525 cw(c11.525,28.775) 11.275,28.775 11.275,30.35 cw(c11.525,30.35) 11.525,30.6 14.875,30.6 cw(c14.875,30.325) 15.15,30.325 15.155,26.48 cw(c14.525,26.48) 14.525,25.85 11.975,25.85 cw(c11.975,26.075)
Bottom Layer:
  pour cut-out: 23.845,39.935 cw(c23.845,39.135) 24.645,39.135 cw(c23.845,39.135) 23.845,38.335 cw(c23.845,39.135) 23.045,39.135 cw(c23.845,39.135)

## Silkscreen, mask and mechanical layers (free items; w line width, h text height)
Top Overlay:
  lines w0.1: 30,1 30,49.8 ccw(c28.8,49.8) 28.8,51 1.2,51 ccw(c1.2,49.8) 0,49.8 0,1 ccw(c1,1) 1,0 28.8,0 ccw(c28.8,1.2) 30,1.2
Bottom Overlay:
  lines w0.1: 0,1 0,49.8 cw(c1.2,49.8) 1.2,51 28.8,51 cw(c28.8,49.8) 30,49.8 30,1.1 ; 0,1.2 ccw(c1.2,1.2) 1.2,0 28.8,0 ccw(c28.8,1.2) 30,1.2
Top Solder:
  drawing of 282 lines, arcs and shapes, not listed
Bottom Solder:
  drawing of 282 lines, arcs and shapes, not listed
BOARD OUTLINE 1:
  drawing of 282 lines, arcs and shapes, not listed
Mechanical 2:
  lines w0.1: -0.5,-0.5 0.5,-0.5 ; 0,-1 0,0
EXT_SILKP 21:
  region: 2.184,1.323 1.815,1.323 1.815,4.45 2.184,4.45
  region: 3.184,1.323 2.815,1.323 2.815,4.575 3.184,4.575
  region: 4.185,1.323 3.815,1.323 3.815,4.7 4.185,4.7
  region: 5.184,1.323 4.815,1.323 4.815,4.825 5.184,4.825
  region: 6.184,1.323 5.815,1.323 5.815,4.95 6.184,4.95
  region: 7.184,1.323 6.815,1.323 6.815,5.075 7.184,5.075
  region: 8.184,1.323 7.815,1.323 7.815,5.2 8.184,5.2
  region: 9.185,1.323 8.815,1.323 8.815,5.325 9.185,5.325
  region: 10.185,1.323 9.815,1.323 9.815,5.45 10.185,5.45
  region: 11.184,1.323 10.815,1.323 10.815,5.575 11.184,5.575
  region: 12.184,1.323 11.815,1.323 11.815,5.7 12.184,5.7
  region: 13.184,1.323 12.815,1.323 12.815,5.825 13.184,5.825
  region: 14.184,1.323 13.815,1.323 13.815,5.95 14.184,5.95
  region: 22.185,1.323 21.815,1.323 21.815,6.95 22.185,6.95
  region: 23.184,1.323 22.815,1.323 22.815,7.075 23.184,7.075
  region: 24.184,1.323 23.815,1.323 23.815,7.2 24.184,7.2
  region: 25.184,1.323 24.815,1.323 24.815,7.325 25.184,7.325
  region: 26.185,1.323 25.815,1.323 25.815,7.45 26.185,7.45
  region: 27.185,1.323 26.815,1.323 26.815,7.575 27.185,7.575
  region: 28.185,1.323 27.815,1.323 27.815,7.7 28.185,7.7
  region: 15.185,1.323 14.815,1.323 14.815,6.075 15.185,6.075
  region: 16.185,1.323 15.815,1.323 15.815,6.2 16.185,6.2
  region: 17.184,1.323 16.815,1.323 16.815,6.325 17.184,6.325
  region: 18.184,1.323 17.815,1.323 17.815,6.45 18.184,6.45
  region: 19.184,1.323 18.815,1.323 18.815,6.575 19.184,6.575
  region: 20.184,1.323 19.815,1.323 19.815,6.7 20.184,6.7
  region: 21.185,1.323 20.815,1.323 20.815,6.825 21.185,6.825
  text "Mighty Gecko" at 0.825,47.3 h3.85
  text "2.4 GHz" at 1,45 h1.9
  text "915 MHz" at 15,45 h1.9
  text "19 dBm" at 1,43 h1.9
  text "19 dBm" at 15,43 h1.9
  text "EFR32MG12" at 10.5,14.5 h1.9
  text "TOUCH SLIDER" at 9,7.5 h1.9
EXT_SILKS 22:
  lines w0.152: 4.173,17.9 4.173,17.6 4.473,17.6 ; 4.173,19.15 4.173,19.45 4.473,19.45 ; 4.823,17.6 5.123,17.6 5.123,17.9 ; 5.123,18.15 5.123,18.45 5.423,18.45 ; 5.723,18.45 6.048,18.45 6.048,18.75 ; 5.723,19.45 6.048,19.45 6.048,19.15
  text "BOARD INFO" at 20.55,49.35 h1.6
  text "PCB4164A  Rev A01" at 28.6,32 h1.6 r90
  text "PAVDD" at 6.829,20.061 h1.6
  text "VDCDC" at 9.823,18.575 h1.2
  text "VMCU" at 3.977,18.457 h1.2
EXT_SILKP 23:
  region: 21.185,1.323 20.815,1.323 20.815,6.825 21.185,6.825
  region: 20.184,1.323 19.815,1.323 19.815,6.7 20.184,6.7
  region: 19.184,1.323 18.815,1.323 18.815,6.575 19.184,6.575
  region: 18.184,1.323 17.815,1.323 17.815,6.45 18.184,6.45
  region: 17.184,1.323 16.815,1.323 16.815,6.325 17.184,6.325
  region: 16.185,1.323 15.815,1.323 15.815,6.2 16.185,6.2
  region: 15.185,1.323 14.815,1.323 14.815,6.075 15.185,6.075
  region: 28.185,1.323 27.815,1.323 27.815,7.7 28.185,7.7
  region: 27.185,1.323 26.815,1.323 26.815,7.575 27.185,7.575
  region: 26.185,1.323 25.815,1.323 25.815,7.45 26.185,7.45
  region: 25.184,1.323 24.815,1.323 24.815,7.325 25.184,7.325
  region: 24.184,1.323 23.815,1.323 23.815,7.2 24.184,7.2
  region: 23.184,1.323 22.815,1.323 22.815,7.075 23.184,7.075
  region: 22.185,1.323 21.815,1.323 21.815,6.95 22.185,6.95
  region: 14.184,1.323 13.815,1.323 13.815,5.95 14.184,5.95
  region: 13.184,1.323 12.815,1.323 12.815,5.825 13.184,5.825
  region: 12.184,1.323 11.815,1.323 11.815,5.7 12.184,5.7
  region: 11.184,1.323 10.815,1.323 10.815,5.575 11.184,5.575
  region: 10.185,1.323 9.815,1.323 9.815,5.45 10.185,5.45
  region: 9.185,1.323 8.815,1.323 8.815,5.325 9.185,5.325
  region: 8.184,1.323 7.815,1.323 7.815,5.2 8.184,5.2
  region: 7.184,1.323 6.815,1.323 6.815,5.075 7.184,5.075
  region: 6.184,1.323 5.815,1.323 5.815,4.95 6.184,4.95
  region: 5.184,1.323 4.815,1.323 4.815,4.825 5.184,4.825
  region: 4.185,1.323 3.815,1.323 3.815,4.7 4.185,4.7
  region: 3.184,1.323 2.815,1.323 2.815,4.575 3.184,4.575
  region: 2.184,1.323 1.815,1.323 1.815,4.45 2.184,4.45
  text "Flex Gecko" at 0.825,47.3 h3.85
  text "2.4 GHz" at 1,45 h1.9
  text "915 MHz" at 15,45 h1.9
  text "19 dBm" at 1,43 h1.9
  text "19 dBm" at 15,43 h1.9
  text "EFR32FG12" at 10.5,14.5 h1.9
  text "TOUCH SLIDER" at 9,7.5 h1.9
EXT_SILKS 24:
  lines w0.152: 4.173,17.9 4.173,17.6 4.473,17.6 ; 4.173,19.15 4.173,19.45 4.473,19.45 ; 4.823,17.6 5.123,17.6 5.123,17.9 ; 5.123,18.15 5.123,18.45 5.423,18.45 ; 5.723,18.45 6.048,18.45 6.048,18.75 ; 5.723,19.45 6.048,19.45 6.048,19.15
  text "BOARD INFO" at 20.55,49.35 h1.6
  text "PCB4253A  Rev A01" at 28.6,32 h1.6 r90
  text "PAVDD" at 6.829,20.061 h1.6
  text "VDCDC" at 9.823,18.575 h1.2
  text "VMCU" at 3.977,18.457 h1.2
Mechanical 26:
  lines w0.2: -125.405,-41.962 -120.405,-41.962 ; -125.405,5.038 -120.405,5.038 ; -125.393,52.038 -120.405,52.038 ; -54.197,-88.993 -54.197,-83.993 ; -54.197,96.007 -54.197,101.007 ; 17.103,-88.993 17.103,-83.993 ; 17.103,96.007 17.103,101.007 ; 88.303,-88.993 88.303,-83.993 ; 88.303,96.007 88.303,101.007 ; 154.595,-41.962 159.595,-41.962 ; 154.595,5.038 159.595,5.038 ; 154.595,52.038 159.583,52.038 ; -125.393,-88.993 -125.393,100.999 159.595,100.999 159.595,-88.993 -125.393,-88.993 ; -120.405,-83.993 -120.405,96.007 154.595,96.007 154.595,-83.993 -120.405,-83.993
  text "1" at -92.505,97.578 h1.52
  text "2" at -20.197,97.578 h1.52
  text "3" at 52.403,97.578 h1.52
  text "4" at 123.203,97.578 h1.52
  text "D" at 156.593,78.438 h1.52
  text "D" at -123.518,77.233 h1.52
  text "C" at -123.518,29.738 h1.52
  text "C" at 156.466,29.738 h1.52
  text "B" at -123.518,-17.862 h1.52
  text "B" at 156.466,-17.862 h1.52
  text "A" at -123.518,-65.362 h1.52
  text "A" at 156.466,-65.362 h1.52
  text "2" at -20.197,-87.435 h1.52
  text "3" at 52.103,-87.435 h1.52
  text "4" at 122.803,-87.435 h1.52
  text "1" at -105.035,-100.91 h1.52
Mechanical 27:
  circle w0.152: c70.608,-62.539 r0.762
  circle w0.152: c70.608,-62.539 r1.778
  circle w0.254: c38.623,-76.995 r2.962
  lines w0.152: 59.609,-62.539 66.975,-62.539 ; 68.322,-62.539 72.894,-62.539 ; 60.371,-63.301 66.188,-64.317 66.213,-60.761 60.371,-61.777 60.371,-63.301
  lines w0.2: 34.575,-83.929 34.575,-57.069 74.589,-57.069 ; 34.575,-69.705 154.539,-69.705 ; 34.589,-66.069 74.589,-66.069 ; 54.869,-83.878 54.869,-69.781 ; 54.869,-66.022 54.869,-57.107 ; 134.589,-69.68 134.589,-66.069 ; 144.589,-66.069 144.589,-57.069 ; 154.589,-66.069 74.589,-66.069 ; 154.589,-57.069 74.589,-57.069 ; 74.589,-66.069 74.589,-57.069
  text "SIZE" at 36.589,-59.069 h1.52
  text "DOC NO" at 76.589,-59.069 h1.52
  text "REV" at 146.589,-59.069 h1.52
  text "PROJECTION" at 55.885,-59.418 h1.52
  text "A01" at 146.309,-63.99 h2.54
  text "A4" at 39.239,-64.444 h2.54
  text "PCB4164/PCB4253" at 79.088,-64.444 h2.54
  text "REF" at 36.589,-68.069 h1.52
  text "SHEET" at 135.589,-68.069 h1.52
  text "1 of 2" at 145.43,-69.106 h1.52
  text "This drawing is confidential and is supplied on the express" at 55.352,-72.677 h1.52
  text "condition that it shall not be loaned, copied or disclosed to any" at 55.352,-75.217 h1.52
  text "other person or used for any purpose without the written consent of" at 55.352,-77.757 h1.52
  text "C" at 38.029,-78.011 h2.03
  text "2016" at 43.109,-78.163 h2.54
  text "SILICON LABS" at 55.784,-82.05 h2.54
Mechanical 28:
  lines w0.2: -125.329,-42.038 -120.329,-42.038 ; -125.329,4.962 -120.329,4.962 ; -125.317,51.962 -120.329,51.962 ; 154.671,-42.038 159.671,-42.038 ; 154.671,51.962 159.671,51.962
  lines w0.203: -120.354,-84.07 -120.354,95.93 ; -120.329,-84.07 154.671,-84.07 154.671,95.93 -120.329,95.93 ; -54.121,-89.07 -54.121,-84.07 ; -54.121,95.93 -54.121,100.93 ; 17.179,-89.07 17.179,-84.07 ; 17.179,95.93 17.179,100.93 ; 88.379,-89.07 88.379,-84.07 ; 88.379,95.93 88.379,100.93 ; -125.317,-89.07 159.671,-89.07 159.671,100.922 -125.317,100.922 -125.317,-89.07
  text "4" at -91.412,97.502 h1.52
  text "3" at -19.105,97.502 h1.52
  text "2" at 53.495,97.502 h1.52
  text "1" at 124.295,97.502 h1.52
  text "D" at 157.685,78.362 h1.52
  text "D" at -122.426,77.157 h1.52
  text "C" at -122.426,29.662 h1.52
  text "C" at 157.685,28.062 h1.52
  text "B" at -122.426,-17.938 h1.52
  text "B" at 157.685,-19.038 h1.52
  text "A" at 156.667,-65.362 h1.52
  text "A" at -122.426,-65.438 h1.52
  text "A" at 157.558,-65.438 h1.52
  text "3" at -19.105,-87.512 h1.52
  text "2" at 53.042,-87.512 h1.52
  text "1" at 123.895,-87.512 h1.52
  text "4" at -103.943,-100.987 h1.52
Mechanical 29:
  circle w0.152: c-36.251,-62.603 r0.762
  circle w0.152: c-36.251,-62.603 r1.778
  circle w0.254: c-4.266,-77.059 r2.962
  lines w0.152: -38.537,-62.603 -33.965,-62.603 ; -32.619,-62.603 -25.253,-62.603 ; -31.857,-60.825 -31.831,-64.381 -26.015,-63.365 -26.015,-61.841 -31.857,-60.825
  lines w0.2: -120.232,-66.134 -40.232,-66.134 ; -120.232,-57.134 -40.232,-57.134 ; -120.182,-69.769 -0.218,-69.769 ; -110.232,-66.134 -110.232,-57.134 ; -100.232,-69.744 -100.232,-66.134 ; -20.512,-83.943 -20.512,-69.846 ; -20.512,-66.086 -20.512,-57.171 ; -0.232,-66.134 -40.232,-66.134 ; -0.232,-57.134 -40.232,-57.134 ; -0.218,-83.993 -0.218,-57.069 ; -40.232,-66.134 -40.232,-57.134
  text "REV" at -112.232,-59.134 h1.52
  text "DOC NO" at -42.232,-59.134 h1.52
  text "SIZE" at -2.232,-59.134 h1.52
  text "PROJECTION" at -21.528,-59.482 h1.52
  text "A01" at -111.952,-64.054 h2.54
  text "PCB4164/PCB4253" at -44.731,-64.508 h2.54
  text "A4" at -4.882,-64.508 h2.54
  text "SHEET" at -101.232,-68.134 h1.52
  text "REF" at -2.232,-68.134 h1.52
  text "2 of 2" at -110.92,-69.106 h1.52
  text "This drawing is confidential and is supplied on the express" at -20.995,-72.741 h1.52
  text "condition that it shall not be loaned, copied or disclosed to any" at -20.995,-75.281 h1.52
  text "other person or used for any purpose without the written consent of" at -20.995,-77.821 h1.52
  text "C" at -3.672,-78.075 h2.03
  text "2016" at -8.752,-78.228 h2.54
  text "SILICON LABS" at -21.427,-82.114 h2.54
Mechanical 30:
  lines w0.2: 34.575,-57.069 34.575,-36.23 154.575,-36.23 ; 34.575,-53.134 74.575,-53.134 ; 34.575,-49.134 74.575,-49.134 154.575,-49.135 ; 34.575,-45.134 74.575,-45.134 ; 74.575,-41.134 154.575,-41.134 ; 74.581,-57.069 74.581,-36.23 ; 74.581,-36.019 74.581,-25.825 154.625,-25.825
  text "BRD4164A: EFR32MG12  2.4 GHz/915 MHz  19 dBm" at 75.65,-28.75 h1.8
  text "BRD4253A: EFR32FG12  2.4 GHz/915 MHz  19 dBm" at 75.7,-31.875 h1.8
  text "CUSTOMER" at 75.683,-38.146 h1.27
  text "PROJECT NO" at 36.059,-39.162 h1.52
  text "SILICON LABS" at 93.125,-40 h2.5
  text "DRAWING TITLE" at 75.912,-43.074 h1.52
  text "BRD4164/BRD4253" at 37.329,-43.607 h2
  text "DATE" at 36.059,-47.29 h1.52
  text "EFR32MG Dual Band Radio Board" at 75.825,-47.325 h1.8
  text "2016-11-17" at 54.347,-48.306 h1.52
  text "SHEET NAME" at 75.709,-51.227 h1.52
  text "DRAWN" at 36.059,-51.354 h1.52
  text "CHECK" at 36.059,-55.418 h1.52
